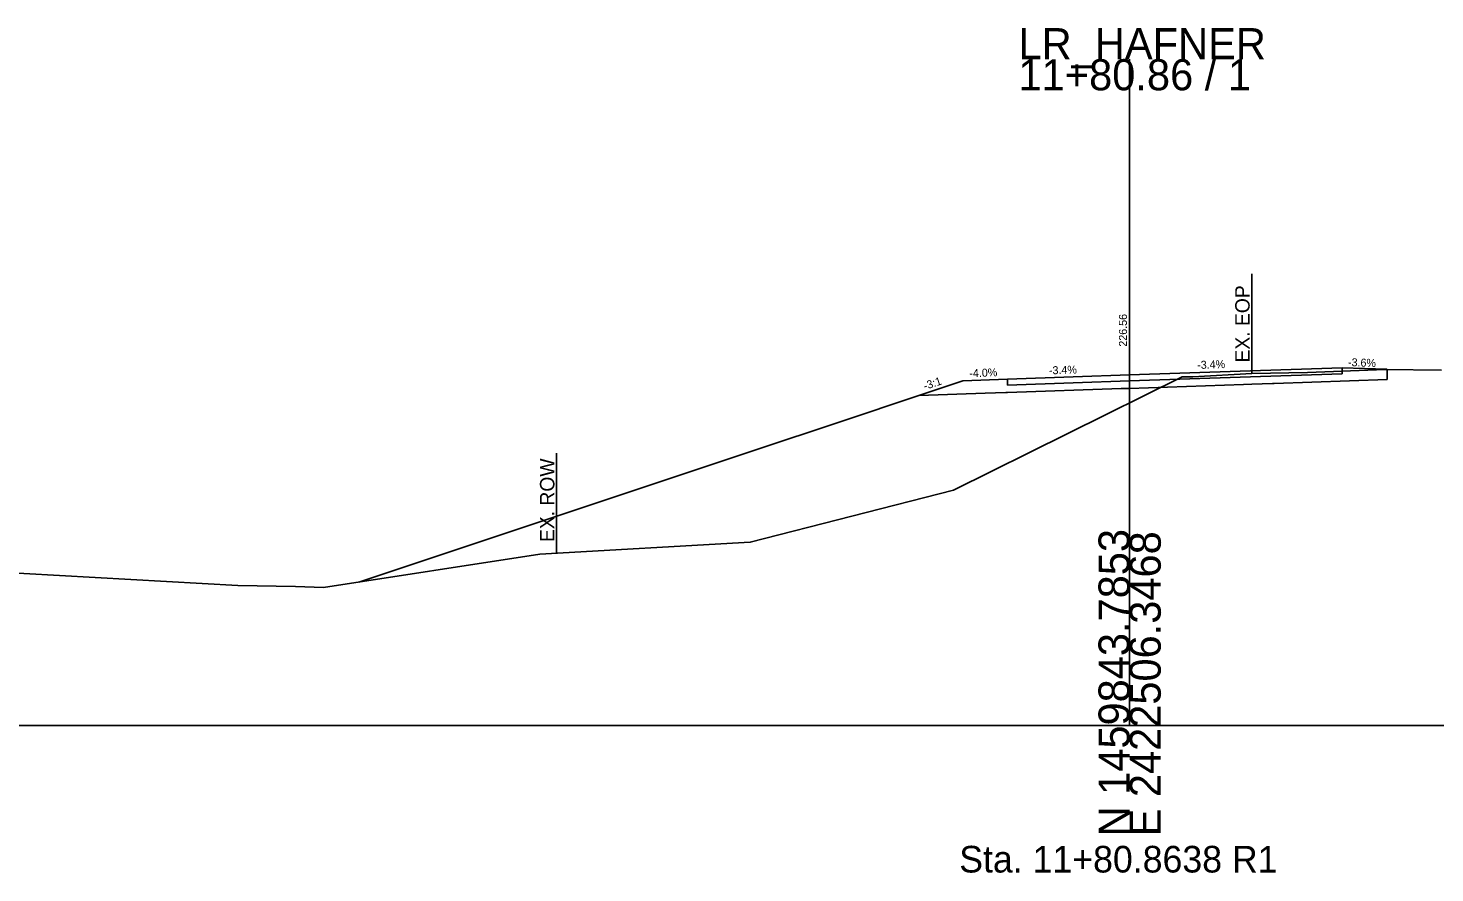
# Model space of a CAD drawing. Extents: x -26 to 403, y -13 to 3053.
# Drawn here: x 100.9 to 227.5, y 986.7 to 1062.8 of the extents above; entities that cross this region are included whole.
import ezdxf

# ---------------------------------------------------------------- set-up
doc = ezdxf.new("R2010")
doc.units = 0
for name, color, linetype in [('CONST_DCH', 7, 'Continuous'), ('Draft_XS_Text', 7, 'Continuous'), ('DTM_CORRIDOR', 7, 'Continuous'), ('DTM_TEMP_DROP', 7, 'Continuous'), ('DTM_X_GROUND', 7, 'Continuous'), ('X_ROW', 7, 'Continuous'), ('X_ROW_TX', 7, 'Continuous'), ('X_TRANS_EOP', 7, 'Continuous'), ('XS_CELL', 7, 'Continuous'), ('XS_P_ASPHALT', 7, 'Continuous'), ('XS_P_GROUND', 7, 'Continuous'), ('XS_P_SHOULDER', 7, 'Continuous'), ('XS_P_SUBGRADE_GRANULAR', 7, 'Continuous'), ('XS_P_TX_CLEARZONE', 7, 'Continuous'), ('XS_P_TX_FS_BS', 7, 'Continuous')]:
    doc.layers.add(name, color=color, linetype=linetype)

msp = doc.modelspace()

# ---------------------------------------------------------------- linework, layer by layer
at = {"layer": 'DTM_X_GROUND'}
msp.add_lwpolyline([(0, 1014.92), (6.49, 1015.03), (8.03, 1014.82), (9.59, 1014.98), (11.7, 1015.04), (15.66, 1015.11), (23.93, 1015.34), (40.06, 1015.36), (65.98, 1015.42), (77.99, 1014.95), (119.77, 1012.6), (124.93, 1012.51), (127.47, 1012.42), (146.94, 1015.42), (165.87, 1016.5), (184.15, 1021.19), (204.73, 1031.38), (204.74, 1031.38), (205.7, 1031.4), (211, 1031.68), (216, 1031.77), (222.98, 1032.05), (228.07, 1031.99)], dxfattribs=at)
at = {"layer": 'X_ROW'}
msp.add_line((148.44, 1024.51), (148.44, 1015.51), dxfattribs=at)
at = {"layer": 'X_TRANS_EOP'}
msp.add_line((211, 1040.68), (211, 1031.68), dxfattribs=at)
at = {"layer": 'XS_CELL'}
for p, q in [((200, 1000), (200, 1060)), ((0, 1000), (200, 1000)), ((200, 1000), (400, 1000))]:
    msp.add_line(p, q, dxfattribs=at)
at = {"layer": 'XS_P_ASPHALT'}
for p, q in [((209.95, 1031.89), (200, 1031.56)), ((219.13, 1032.21), (209.95, 1031.89)), ((209.95, 1031.35), (219.13, 1031.67)), ((219.13, 1031.67), (219.13, 1032.21)), ((194.91, 1031.38), (189, 1031.19)), ((189, 1031.19), (189, 1030.65)), ((189, 1030.65), (194.91, 1030.84)), ((200, 1031.56), (194.91, 1031.38)), ((194.91, 1030.84), (200, 1031.02)), ((200, 1031.02), (209.95, 1031.35))]:
    msp.add_line(p, q, dxfattribs=at)
at = {"layer": 'XS_P_GROUND'}
for points in [[(223.13, 1032.07), (223.18, 1032.05)], [(130.63, 1012.91), (169.26, 1025.78), (171, 1026.36), (183.99, 1030.69), (185, 1031.03)]]:
    msp.add_lwpolyline(points, dxfattribs=at)
at = {"layer": 'XS_P_SHOULDER'}
for points in [[(219.13, 1032.21), (223.13, 1032.07)], [(189, 1031.19), (185, 1031.03)]]:
    msp.add_lwpolyline(points, dxfattribs=at)
at = {"layer": 'XS_P_SUBGRADE_GRANULAR'}
msp.add_line((223.18, 1032.05), (223.18, 1031.14), dxfattribs=at)
for points in [[(211, 1030.73), (210.25, 1030.7), (200, 1030.35)], [(223.18, 1031.14), (213, 1030.79), (212.87, 1030.79), (211, 1030.73)], [(181.05, 1029.71), (187, 1029.91), (188.87, 1029.97), (189, 1029.98)], [(189, 1029.98), (199.25, 1030.33), (200, 1030.35)]]:
    msp.add_lwpolyline(points, dxfattribs=at)

# ---------------------------------------------------------------- texts
at = {"layer": 'CONST_DCH'}
for p in [(211, 1031.93), (219.13, 1032.2), (189, 1031.18), (200, 1031.55)]:
    msp.add_text('X', height=0.012, dxfattribs=at).set_placement(p)
at = {"layer": 'Draft_XS_Text'}
msp.add_text('Sta. 11+80.8638 R1', height=2.4, dxfattribs=at).set_placement((184.67, 986.75))
at = {"layer": 'DTM_CORRIDOR'}
msp.add_text('X', height=0.012, dxfattribs=at).set_placement((171, 1026.35))
at = {"layer": 'DTM_TEMP_DROP'}
msp.add_text('X', height=0.012, dxfattribs=at).set_placement((185, 1031.02))
at = {"layer": 'X_ROW_TX'}
msp.add_text('EX. ROW', height=1.3, rotation=90, dxfattribs=at).set_placement((148.24, 1016.51))
at = {"layer": 'X_TRANS_EOP'}
msp.add_text('EX. EOP', height=1.3, rotation=90, dxfattribs=at).set_placement((210.8, 1032.68))
at = {"layer": 'XS_CELL'}
for s, p in [('LR_HAFNER', (190, 1060)), ('11+80.86 / 1', (190, 1057.2))]:
    msp.add_text(s, height=2.8, dxfattribs=at).set_placement(p)
for s, p in [('N 1459843.7853', (200, 990)), ('E 2422506.3468', (202.8, 990))]:
    msp.add_text(s, height=2.8, rotation=90, dxfattribs=at).set_placement(p)
at = {"layer": 'XS_P_ASPHALT'}
msp.add_text('X', height=0.012, dxfattribs=at).set_placement((150.24, 1019.44))
at = {"layer": 'XS_P_GROUND'}
msp.add_text('X', height=0.012, dxfattribs=at).set_placement((150.24, 1019.44))
at = {"layer": 'XS_P_TX_CLEARZONE'}
msp.add_text('226.56', height=0.72, rotation=90, dxfattribs=at).set_placement((199.76, 1034.11))
at = {"layer": 'XS_P_TX_FS_BS'}
for s, rotation, p in [('-3.4%', 1.9424, (206.09, 1032.1)), ('-3.6%', 357.9356, (219.64, 1032.36)), ('-4.0%', 2.2906, (185.59, 1031.35)), ('-3.4%', 1.9421, (192.75, 1031.61)), ('-3:1', 18.4349, (181.58, 1030.2))]:
    msp.add_text(s, height=0.72, rotation=rotation, dxfattribs=at).set_placement(p)

doc.saveas('drawing.dxf')
